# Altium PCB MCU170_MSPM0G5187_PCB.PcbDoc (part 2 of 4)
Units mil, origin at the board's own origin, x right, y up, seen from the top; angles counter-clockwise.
Board outline 2300 x 4450 mil, 4 copper layers (Top Layer, VCC Layer, GND Layer, Bottom Layer), stack 62.4 mil thick; 276 components, 190 nets, 913 pads, 323 vias.
Unrouted connection lines stored in the file: 4.
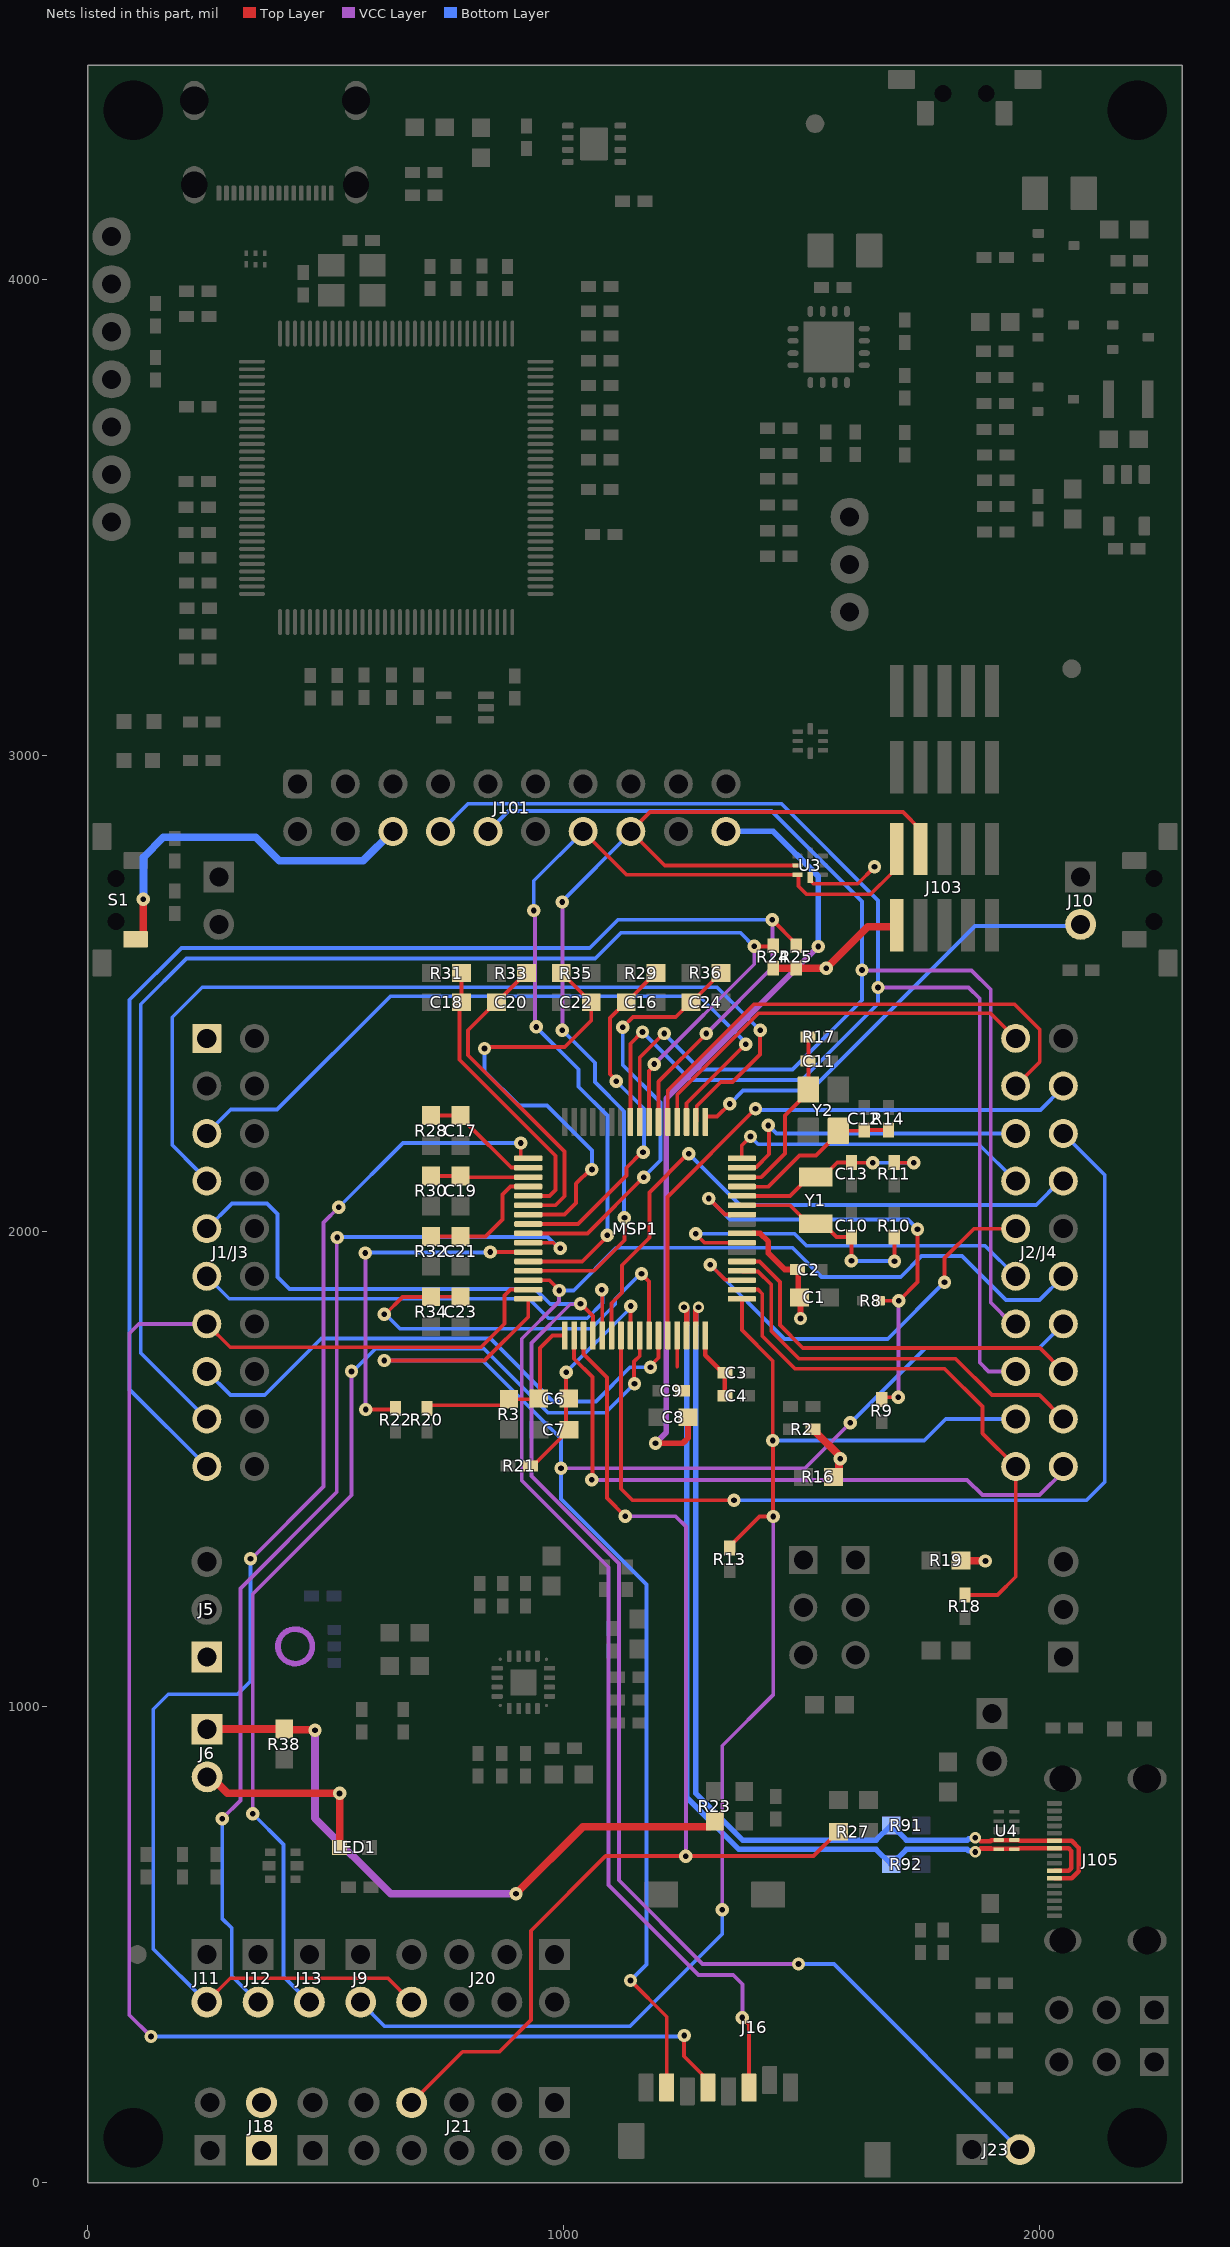
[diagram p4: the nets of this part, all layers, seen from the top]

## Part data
C1 C35 C69: library part CMP-0007304-1, "CAP, CERM, 10 uF, 6.3 V, +/- 20%, X5R, 0603", Cap_Case=0603, Manufacturer=MuRata, Supplier Part Number 1=490-7316-1-ND, TempCo=X5R, Tolerance_%=20%, Value1=Unknown, Value2=6.3V, ValueDisplayed=10uF
C2 C9 C31 C72 C73 C74 C75: library part CMP-0006614-2, "CAP, CERM, 0.1 uF, 50 V, +/- 20%, X5R, 0402", Cap_Case=0402, Manufacturer=MuRata, Supplier Part Number 1=GRM155R61H104ME14D-ND, TempCo=X5R, Tolerance_%=20%, Value1=Unknown, Value2=50V, ValueDisplayed=0.1uF
C3: library part CMP-0006551-2, "CAP, CERM, 0.47 uF, 6.3 V, +/- 10%, X5R, 0402", Cap_Case=0402, Manufacturer=MuRata, Supplier Part Number 1=490-3266-1-ND, TempCo=X5R, Tolerance_%=10%, Value1=Unknown, Value2=6.3V, ValueDisplayed=0.47uF
C4: library part CMP-0006614-2, "CAP, CERM, 0.1 uF, 50 V, +/- 20%, X5R, 0402", Cap_Case=0402, Manufacturer=MuRata, Supplier Part Number 1=GRM155R61H104ME14D-ND, TempCo=X5R, Tolerance_%=20%, Value1=Unknown, Value2=50V, ValueDisplayed=DNC
C5: library part CMP-0006590-2, "CAP, CERM, 0.01 uF, 16 V, +/- 10%, X5R, 0402", Cap_Case=0402, Manufacturer=MuRata, Supplier Part Number 1=GRM155R61C103KA01D-ND, TempCo=X5R, Tolerance_%=10%, Value1=Unknown, Value2=16V, ValueDisplayed=0.01uF
C6 C7 C8: library part CMP-0007006-5, "CAP, CERM, 1 uF, 25 V, +/- 10%, X5R, 0603", Cap_Case=0603, Manufacturer=TDK, Supplier Part Number 1=445-5146-1-ND, TempCo=X5R, Tolerance_%=10%, Value1=Unknown, Value2=25V, ValueDisplayed=DNC
C10 C11 C12 C13: library part CMP-0006420-2, "CAP, CERM, 15 pF, 50 V, +/- 5%, C0G/NP0, 0402", Cap_Case=0402, Manufacturer=MuRata, Supplier Part Number 1=81-GRM1555C1H150JA1D, TempCo=C0G/NP0, Tolerance_%=5%, Value1=Unknown, Value2=50V, ValueDisplayed=15pF
C14: library part CMP-0078241-1, "CAP, CERM, 0.1 µF, 10 V,+/- 10%, X7R, 0402", Cap_Case=0402, Manufacturer=Kemet, Supplier Part Number 1=399-3520-1-ND, TempCo=X7R, Tolerance_%=10%, Value2=10V, ValueDisplayed=0.1µF
C15 C36: library part CMP-0007122-5, "CAP, CERM, 10 uF, 16 V, +/- 20%, X5R, 0603", Cap_Case=0603, Manufacturer="Taiyo Yuden", Supplier Part Number 1=587-3238-1-ND, TempCo=X5R, Tolerance_%=20%, Value1=Unknown, Value2=16V, ValueDisplayed=10uF
C16 C17 C18 C19 C20 C21 C22 C23 C24: library part CMP-0007135-4, "CAP, CERM, 0.1 uF, 16 V, +/- 10%, X7R, AEC-Q200 Grade 1, 0603", Cap_Case=0603, Manufacturer=MuRata, Supplier Part Number 1=490-8015-1-ND, TempCo=X7R, Tolerance_%=10%, Value1=Unknown, Value2=16V, ValueDisplayed=0.1uF
C25 C26 C33 C34: library part CMP-0006563-2, "CAP, CERM, 1 uF, 10 V, +/- 10%, X5R, 0402", Cap_Case=0402, Manufacturer=MuRata, Supplier Part Number 1=490-3890-1-ND, TempCo=X5R, Tolerance_%=10%, Value1=Unknown, Value2=10V, ValueDisplayed=1uF
C27 C28 C29: library part CMP-0007023-4, "CAP, CERM, 10 uF, 10 V, +/- 10%, X6S, 0603", Cap_Case=0603, Manufacturer=TDK, Supplier Part Number 1=445-9019-1-ND, TempCo=X6S, Tolerance_%=10%, Value1="0.004639 ohm", Value2=10V, ValueDisplayed=10uF
C30 C32: library part CMP-0007037-4, "CAP, CERM, 1 uF, 16 V, +/- 10%, X7R, 0603", Cap_Case=0603, Manufacturer=TDK, Supplier Part Number 1=445-1604-1-ND, TempCo=X7R, Tolerance_%=10%, Value1="0.0057 ohm", Value2=16V, ValueDisplayed=1uF
C37 C41 C42 C44 C48 C51 C52 C57 C62 C63 C68: library part CMP-0006623-2, "CAP, CERM, 0.1 uF, 6.3 V, +/- 10%, X7R, 0402", Cap_Case=0402, Manufacturer=MuRata, Supplier Part Number 1=GRM155R70J104KA01D-ND, TempCo=X7R, Tolerance_%=10%, Value1=Unknown, Value2=6.3V, ValueDisplayed=0.1uF
C38 C39 C40 C46 C50: library part CMP-0006658-2, "CAP, CERM, 0.01 uF, 25 V, +/- 10%, X7R, 0402", Cap_Case=0402, Manufacturer=MuRata, Supplier Part Number 1=490-1312-1-ND, TempCo=X7R, Tolerance_%=10%, Value1=Unknown, Value2=25V, ValueDisplayed=0.01uF
C43 C45 C49 C70: library part CMP-0006276-2, "CAP, CERM, 1 uF, 25 V, +/- 10%, X5R, 0402", Cap_Case=0402, Manufacturer=TDK, Supplier Part Number 1=445-9066-1-ND, TempCo=X5R, Tolerance_%=10%, Value1=Unknown, Value2=25V, ValueDisplayed=1uF
C47 C71: library part CMP-0006543-2, "CAP, CERM, 2.2 uF, 6.3 V, +/- 10%, X5R, 0402", Cap_Case=0402, Manufacturer=MuRata, Supplier Part Number 1=81-GRM155R60J225KE5D, TempCo=X5R, Tolerance_%=10%, Value1=Unknown, Value2=6.3V, ValueDisplayed=2.2uF
C53 C54: library part CMP-0006415-2, "CAP, CERM, 12 pF, 50 V, +/- 5%, C0G/NP0, 0402", Cap_Case=0402, Manufacturer=MuRata, Supplier Part Number 1=14T3292, TempCo=C0G/NP0, Tolerance_%=5%, Value1=Unknown, Value2=50V, ValueDisplayed=12pF
C55 C58: library part CMP-0006454-1, "CAP, CERM, 33 pF, 50 V, +/- 5%, C0G/NP0, 0402", Cap_Case=0402, Manufacturer=MuRata, Supplier Part Number 1=81-GRM1555C1H330JA1D, TempCo=C0G/NP0, Tolerance_%=5%, Value1=Unknown, Value2=50V, ValueDisplayed=33pF
C56 C60: library part CMP-0011480-1, "CAP, TA, 4.7 uF, 16 V, +/- 10%, 4 ohm, SMD", Cap_Case=3216-18, Manufacturer=AVX, Supplier Part Number 1=478-3868-1-ND, Tolerance_%=10%, Value1="4 ohm", Value2=16V, ValueDisplayed=4.7uF
C59: library part CMP-0006354-2, "CAP, CERM, 1000 pF, 50 V, +/- 10%, X7R, AEC-Q200 Grade 1, 0402", Cap_Case=0402, Manufacturer=MuRata, Supplier Part Number 1=490-4761-1-ND, TempCo=X7R, Tolerance_%=10%, Value1=Unknown, Value2=50V, ValueDisplayed=1000pF
C61 C67: library part CMP-0007341-4, "CAP, CERM, 4.7 uF, 16 V, +/- 10%, X5R, 0603", Cap_Case=0603, Manufacturer=MuRata, Supplier Part Number 1=490-10481-1-ND, TempCo=X5R, Tolerance_%=10%, Value1=Unknown, Value2=16V, ValueDisplayed=4.7uF
C64: library part CMP-0007313-1, "CAP, CERM, 47 uF, 6.3 V, +/- 20%, X5R, 0603", Cap_Case=0603, Manufacturer=MuRata, TempCo=X5R, Tolerance_%=20%, Value1=Unknown, Value2=6.3V, ValueDisplayed=47uF
C65 C66: library part CMP-0006648-1, "CAP, CERM, 0.22 uF, 16 V, +/- 10%, X7R, 0402", Cap_Case=0402, Manufacturer=MuRata, Supplier Part Number 1=490-5418-1-ND, TempCo=X7R, Tolerance_%=10%, Value1=Unknown, Value2=16V, ValueDisplayed=0.22uF
C76 C77: library part CMP-0081457-1, "CAP, CERM, 1 µF, 10 V,+/- 20%, X5R, 0402", Cap_Case=0402, Manufacturer="Yageo America", TempCo=X5R, Tolerance_%=20%, Value2=10V, ValueDisplayed=1µF
D1 D2: library part CMP-0028883-1, "Diode, Schottky, 40 V, 0.12 A, AEC-Q101, SOT-323", Manufacturer=Nexperia, Supplier Part Number 1=568-7982-1-ND, Value1=0.12A, Value2=1V
FID1 FID2 FID3: library part CMP-0077181-1, "Fiducial mark.  There is nothing to buy or mount.", Manufacturer=N/A
H1 H2: library part CMP-0077978-1, "Spacer Support, Nylon 66", Manufacturer="Kang Yang"
IC2: library part CMP-0032790-2, "Precision Micropower Shunt Voltage Reference, 0.5% accuracy, 2.5 V, 15 ppm / degC, 15 mA, -40 to 85 degC, 5-pin SC70 (DCK), Green (RoHS & no Sb/Br)", Manufacturer="Texas Instruments", Rating=Catalog, Temp Coeff(Max)(ppm/ degree C)=100, Temp Coeff(Typ)(ppm/ degree C)=15
IC3: library part CMP-0074212-1, "2.7-4V Dual In/Single Out MOSFET, 0.5A Main/0.1A Aux Input, Act-Low Enable, Comm. Temp., DBV0005A (SOT-23-5)", Alternate Manufacturer="Texas Instruments", Alternate PartNumber=TPS2102DBVT
IC4 U3: library part CMP-0043125-2, "Low-Capacitance + / - 15 kV ESD Protection Array for High-Speed Data Interfaces, 6 Channels, -40 to +85 degC, 8-pin UQFN (RSE), Green (RoHS & no Sb/Br)", Breakdown Voltage(Min)(V)=6, IO Capacitance(Typ)(pF)=1.6, IO Leakage Current(nA)=1, Manufacturer="Texas Instruments"
IC5: library part CMP-0043115-1, "ESD-Protection Array for High-Speed Data Interfaces, 4 Channels, -40 to +85 degC, 6-pin SON (DRY), Green (RoHS & no Sb/Br)", Breakdown Voltage(Min)(V)=6, IO Capacitance(Typ)(pF)=1.6, IO Leakage Current(nA)=1, Manufacturer="Texas Instruments"
IC6: library part CMP-0036329-3, "500mA, Adjustable, Low Quiescent Current, Low-Noise, High-PSRR, Single-Output LDO Regulator, DRB0008A (VSON-8)", Manufacturer="Texas Instruments", Operating Temperature Range="-40 to 125 C", Rating=Catalog
J1/J3: library part CMP-0003837-4, "Receptacle, 2.54mm, 10x2, Tin, TH", Alternate Manufacturer="Major League Electronics", Alternate PartNumber=CRD-081413-A-G, Manufacturer=Samtec, Supplier Part Number 1=SAM1204-10-ND
J2/J4: library part CMP-0078266-4, "Receptacle, 2.54mm, 10x2, Tin, TH", Alternate Manufacturer="Major League Electronics", Alternate PartNumber=CRD-081413-A-G, Manufacturer=Samtec, Supplier Part Number 1=SAM1204-10-ND
J5 J7 J14 J15 J24 J25: library part CMP-0002338-1, "Header, 100mil, 3x1, Tin, TH", Color=Black, Current_A=3A, Manufacturer="Sullins Connector Solutions", Supplier Part Number 1=S1012E-03-ND, Voltage_V=1.8kV
J6 J8 J9 J10 J11 J12 J13 J17 J18 J19 J22 J23: library part CMP-0055312-1, "Header, 100mil, 2x1, Tin, TH", Manufacturer=Molex, Supplier Part Number 1=WM8072-ND
J16: library part CMP-0089421-1, "9 (8 + 1) Position Card Connector Secure Digital - microSD™ Surface Mount, Right Angle Gold", Current_A=500mA, Digikey Part Number=732-3819-1-ND, Manufacturer="Wurth Electronics", Mouser Part Number=710-693071010811, Operating Temperature Range="-25°C to +85°C", Voltage_V=100V
J20: library part CMP-0054542-2, "Header, 100mil, 4x2, Tin, TH", Color=Black, Current_A=3A, Manufacturer="Sullins Connector Solutions", Supplier Part Number 1=S2012E-04-ND, Voltage_V=1.8kV
J21: library part CMP-0054550-2, "Header, 100mil, 5x2, Tin, TH", Color=Black, Current_A=3A, Manufacturer="Sullins Connector Solutions", Supplier Part Number 1=S2012E-05-ND, Voltage_V=1.8kV
J101: library part CMP-0054623-2, "Header, 2.54mm, 10x2, Tin, TH", Color=Black, Current_A=3A, Manufacturer="Sullins Connector Solutions", Supplier Part Number 1=S2012E-10-ND
J102 J103: library part CMP-0075634-1, "Header(Shrouded), 1.27mm, 5x2, Gold, SMT", Color=Black, Current_A=3.3A, Manufacturer=Samtec, Supplier Part Number 1=SAM8799-ND
J104 J105: library part CMP-0092121-1, "16PIN USB C connectors in chargers TOP mount type CH 1.63 & L=6.9 USB Type C connectors", Current_A=5A, Manufacturer=MUP, Operating Temperature Range=to
L1: library part CMP-0059590-1, "Inductor, Wirewound, Ceramic, 2.2 uH, 0.89 A, 0.13 ohm, SMD", Manufacturer="Taiyo Yuden", Supplier Part Number 1=587-1618-1-ND, Value1="0.13 ohm", Value2=0.89A, ValueDisplayed=2.2uH
LED1 LED3 LED101: library part CMP-0002972-3, "LED, Red, SMD", Color=Red, Manufacturer="Stanley Electric Co., LTD", Power_TotalModule=57.5mW, Value1=0.0575W, Value2=1.7V
LED2: library part CMP-0074720-1, "LED, RGB, SMD", Color=RGB, Manufacturer=Everlight, Supplier Part Number 1=19-337/R6GHBHC-A01/2T-ND, Value1=W, Value2=3.8V
LED102: library part CMP-0002827-3, "LED, Green, SMD", Color=green, Manufacturer=Lite-On, Power_TotalModule=100mW, Value1=0.1W, Value2=2.1V
LOGO1: library part CMP-0074844-1
Logo2 Logo3: library part CMP-0074838-1, "Texas Instrument Corporate Signature"
Logo4: library part CMP-0074840-1, "ESD Susceptible Symbol"
Logo5: library part CMP-0074847-1, "FCC_disclaimer"
Logo6: library part CMP-0074769-1
MH1 MH2 MH3 MH4: library part CMP-0078424-2, "PCB Mounting Hole, No Pad", Manufacturer=Any, PartNumber=N/A
MSP1: library part CMP-0125668-4, "Mixed-Signal Microcontrollers With USB 2.0-FS Interface and NPU", Frequency_Fixed=80MHz, Manufacturer="Texas Instruments", Max Supply Voltage=3.6V, Min Supply Voltage=1.62V, Operating Temperature Range="-40°C to +125°C"
R1 R2 R40 R42 R43 R44: library part CMP-0026935-1, "RES, 47 k, 5%, 0.063 W, 0402", Manufacturer=Vishay-Dale, Power_W=63mW, Supplier Part Number 1=541-47KJCT-ND, TempCo="200 ppm/C", Tolerance_%=5%, Value2=0.063W, Value_Code=47k0, ValueDisplayed=47k
R3 R23 R38: library part CMP-0025885-5, "RES, 0, 5%, 0.1 W, 0603", Manufacturer=Yageo, Power_W=100mW, Supplier Part Number 1=311-0.0GRCT-ND, TempCo="200 ppm/C", Tolerance_%=5%, Value2=0.1W, Value_Code=0000, ValueDisplayed=DNC
R4 R57 R58: library part CMP-0026934-2, "RES, 470, 5%, 0.063 W, 0402", Manufacturer=Vishay-Dale, Power_W=63mW, Supplier Part Number 1=541-470JCT-ND, TempCo="200 ppm/C", Tolerance_%=5%, Value2=0.063W, Value_Code=470R, ValueDisplayed=470
R5: library part CMP-0026878-1, "RES, 220, 5%, 0.063 W, 0402", Manufacturer=Vishay-Dale, Power_W=63mW, Supplier Part Number 1=541-220JCT-ND, TempCo="200 ppm/C", Tolerance_%=5%, Value2=0.063W, Value_Code=220R, ValueDisplayed=220
R6 R7: library part CMP-0026906-1, "RES, 330, 5%, 0.063 W, 0402", Manufacturer=Vishay-Dale, Power_W=63mW, Supplier Part Number 1=541-330JCT-ND, TempCo="200 ppm/C", Tolerance_%=5%, Value2=0.063W, Value_Code=330R, ValueDisplayed=330
R8: library part CMP-0088648-1, "Res Thin Film 0402 100K Ohm 0.1% 1/16W ±25ppm/°C Molded SMD SMD Punched Carrier T/R", Digikey Part Number=P100KDCCT-ND, Manufacturer=Panasonic, Mouser Part Number=667-ERA-2AEB104X, Octopart Part Number=aea26725a1f47165, Operating Temperature Range="-55°C to +155°C", Power_W=63mW, TempCo=25ppm/°C, Tolerance_%=0.1%, Voltage=25V
R9 R10 R11 R14 R17 R20 R21: library part CMP-0027004-2, "RES, 0, 5%, 0.063 W, 0402", Manufacturer="Yageo America", Power_W=63mW, Supplier Part Number 1=311-0.0JRCT-ND, TempCo="200 ppm/C", Tolerance_%=5%, Value2=0.063W, Value_Code=0000, ValueDisplayed=DNC
R12 R15 R27: library part CMP-0025927-5, "RES, 4.7 k, 5%, 0.1 W, 0603", Manufacturer=Yageo, Power_W=100mW, Supplier Part Number 1=311-4.7KGRCT-ND, TempCo="100 ppm/C", Tolerance_%=5%, Value2=0.1W, Value_Code=4k70, ValueDisplayed=4.7k
R13 R18: library part CMP-0026886-1, "RES, 270, 5%, 0.063 W, 0402", Manufacturer=Vishay-Dale, Power_W=63mW, Supplier Part Number 1=541-270JCT-ND, TempCo="200 ppm/C", Tolerance_%=5%, Value2=0.063W, Value_Code=270R, ValueDisplayed=270
R16 R19: library part CMP-0025906-5, "RES, 2.2 k, 5%, 0.1 W, 0603", Manufacturer=Yageo, PartNumber=RC0603JR-072K2L, Power_W=100mW, Supplier Part Number 1=311-2.2KGRCT-ND, TempCo="100 ppm/C", Tolerance_%=5%, Value2=0.1W, Value_Code=2k20, ValueDisplayed=2.2k
R22: library part CMP-0027004-2, "RES, 0, 5%, 0.063 W, 0402", Manufacturer="Yageo America", Power_W=63mW, Supplier Part Number 1=311-0.0JRCT-ND, TempCo="200 ppm/C", Tolerance_%=5%, Value2=0.063W, Value_Code=0000
R24 R25: library part CMP-0026938-5, "RES, 4.7 k, 5%, 0.063 W, AEC-Q200 Grade 0, 0402", Manufacturer=Vishay-Dale, Power_W=63mW, Supplier Part Number 1=541-4.7KJCT-ND, TempCo="200 ppm/C", Tolerance_%=5%, Value2=0.063W, Value_Code=4k70, ValueDisplayed=DNC
R26: library part CMP-0025925-5, "RES, 47 k, 5%, 0.1 W, 0603", Manufacturer=Yageo, Power_W=100mW, Supplier Part Number 1=311-47KGRCT-ND, TempCo="100 ppm/C", Tolerance_%=5%, Value2=0.1W, Value_Code=47k0, ValueDisplayed=47k
R28 R30 R32 R34: library part CMP-0022928-4, "RES, 22.0, 1%, 0.1 W, 0603", Manufacturer=Yageo, Power_W=100mW, Supplier Part Number 1=311-22.0HRCT-ND, TempCo="100 ppm/C", Tolerance_%=1%, Value2=0.1W, Value_Code=22R0, ValueDisplayed=22.0
R29 R31 R33 R35 R36 R80 R84 R91 R92: library part CMP-0025885-5, "RES, 0, 5%, 0.1 W, 0603", Manufacturer=Yageo, Power_W=100mW, Supplier Part Number 1=311-0.0GRCT-ND, TempCo="200 ppm/C", Tolerance_%=5%, Value2=0.1W, Value_Code=0000, ValueDisplayed=0
R37 R39 R41: library part CMP-0027004-2, "RES, 0, 5%, 0.063 W, 0402", Manufacturer="Yageo America", Power_W=63mW, Supplier Part Number 1=311-0.0JRCT-ND, TempCo="200 ppm/C", Tolerance_%=5%, Value2=0.063W, Value_Code=0000, ValueDisplayed=0
R45 R85: library part CMP-0026731-1, "RES, 330 k, 1%, 0.0625 W, 0402", Manufacturer="Yageo America", Power_W=62.5mW, Supplier Part Number 1=311-330KLRCT-ND, TempCo="100 ppm/C", Tolerance_%=1%, Value2=0.0625W, Value_Code=330k
R46 R64 R65 R71 R72 R79 R82 R87: library part CMP-0026728-1, "RES, 220 k, 1%, 0.0625 W, 0402", Manufacturer="Yageo America", Power_W=62.5mW, Supplier Part Number 1=311-220KLRCT-ND, TempCo="100 ppm/C", Tolerance_%=1%, Value2=0.0625W, Value_Code=220k
R47 R48: library part CMP-0026752-1, "RES, 56.0 k, 1%, 0.063 W, AEC-Q200 Grade 0, 0402", Manufacturer="KOA Speer", Power_W=63mW, Supplier Part Number 1=660-RK73H1ETTP5602F, TempCo="100 ppm/C", Tolerance_%=1%, Value2=0.063W, Value_Code=56k0, ValueDisplayed=56.0k
R49 R50 R86 R88: library part CMP-0026463-2, "RES, 5.11 k, 1%, 0.063 W, AEC-Q200 Grade 0, 0402", Manufacturer=Vishay-Dale, Power_W=63mW, Supplier Part Number 1=541-5.11KLCT-ND, TempCo="100 ppm/C", Tolerance_%=1%, Value2=0.063W, Value_Code=5k11, ValueDisplayed=5.11k
R51: library part CMP-0078193-1, "RES, 1.0 k, 5%, 0.1 W, AEC-Q200 Grade 0, 0402", Manufacturer=Panasonic, Power_W=100mW, Supplier Part Number 1=P1.0KJCT-ND, TempCo="200 ppm/C", Tolerance_%=5%, Value2=0.1W, Value_Code=1k00, ValueDisplayed=1.0k
R52 R53 R54 R62: library part CMP-0026852-1, "RES, 1.0 k, 5%, 0.063 W, 0402", Manufacturer=Vishay-Dale, Power_W=63mW, Supplier Part Number 1=541-1.0KJCT-ND, TempCo="200 ppm/C", Tolerance_%=5%, Value2=0.063W, Value_Code=1k00, ValueDisplayed=1.0k
R55: library part CMP-0026852-1, "RES, 1.0 k, 5%, 0.063 W, 0402", Manufacturer=Vishay-Dale, Power_W=63mW, Supplier Part Number 1=541-1.0KJCT-ND, TempCo="200 ppm/C", Tolerance_%=5%, Value2=0.063W, Value_Code=1k00, ValueDisplayed=DNC
R56: library part CMP-0026824-3, "RES, 100, 5%, 0.063 W, AEC-Q200 Grade 0, 0402", Manufacturer=Vishay-Dale, Power_W=63mW, Supplier Part Number 1=541-100JCT-ND, TempCo="200 ppm/C", Tolerance_%=5%, Value2=0.063W, Value_Code=100R, ValueDisplayed=100
R59 R89 R90: library part CMP-0026825-4, "RES, 10 k, 5%, 0.063 W, 0402", Manufacturer=Vishay-Dale, Power_W=63mW, Supplier Part Number 1=541-10KJCT-ND, TempCo="200 ppm/C", Tolerance_%=5%, Value2=0.063W, Value_Code=10k0, ValueDisplayed=10k
R60: library part CMP-0026413-2, "RES, 4.87 k, 1%, 0.063 W, AEC-Q200 Grade 0, 0402", Manufacturer=Vishay-Dale, Power_W=63mW, Supplier Part Number 1=541-4.87KLCT-ND, TempCo="100 ppm/C", Tolerance_%=1%, Value2=0.063W, Value_Code=4k87, ValueDisplayed=4.87k
R61: library part CMP-0026824-1, "RES, 100, 5%, 0.063 W, 0402", Manufacturer=Vishay-Dale, Power_W=63mW, Supplier Part Number 1=541-100JCT-ND, TempCo="200 ppm/C", Tolerance_%=5%, Value2=0.063W, Value_Code=100R, ValueDisplayed=100
R63: library part CMP-0026946-3, "RES, 51, 5%, 0.063 W, AEC-Q200 Grade 0, 0402", Manufacturer=Vishay-Dale, Power_W=63mW, Supplier Part Number 1=541-51JCT-ND, TempCo="200 ppm/C", Tolerance_%=5%, Value2=0.063W, Value_Code=51R0, ValueDisplayed=51
R66 R83: library part CMP-0026695-1, "RES, 3.30 k, 1%, 0.1 W, AEC-Q200 Grade 0, 0402", Manufacturer=Panasonic, Power_W=100mW, Supplier Part Number 1=P3.30KLCT-ND, TempCo="100 ppm/C", Tolerance_%=1%, Value2=0.1W, Value_Code=3k30, ValueDisplayed=3.30k
R67: library part CMP-0026231-1, "RES, 2.20 k, 1%, 0.063 W, 0402", Manufacturer=Vishay-Dale, Power_W=63mW, Supplier Part Number 1=541-2.20KLCT-ND, TempCo="100 ppm/C", Tolerance_%=1%, Value2=0.063W, Value_Code=2k20, ValueDisplayed=2.20k
R68: library part CMP-0026517-1, "RES, 6.81 k, 1%, 0.063 W, 0402", Manufacturer=Vishay-Dale, Power_W=63mW, Supplier Part Number 1=541-6.81KLCT-ND, TempCo="100 ppm/C", Tolerance_%=1%, Value2=0.063W, Value_Code=6k81, ValueDisplayed=6.81k
R69 R70: library part CMP-0026938-1, "RES, 4.7 k, 5%, 0.063 W, 0402", Manufacturer=Vishay-Dale, Power_W=63mW, Supplier Part Number 1=541-4.7KJCT-ND, TempCo="200 ppm/C", Tolerance_%=5%, Value2=0.063W, Value_Code=4k70, ValueDisplayed=4.7k
R73 R74 R77: library part CMP-0026737-1, "RES, 47.0 k, 1%, 0.0625 W, 0402", Manufacturer="Yageo America", Power_W=62.5mW, Supplier Part Number 1=311-47.0KLRCT-ND, TempCo="100 ppm/C", Tolerance_%=1%, Value2=0.0625W, Value_Code=47k0, ValueDisplayed=47.0k
R75: library part CMP-0026743-1, "RES, 820, 1%, 0.063 W, 0402", Manufacturer="Yageo America", Power_W=63mW, Supplier Part Number 1=311-820LRCT-ND, TempCo="100 ppm/C", Tolerance_%=1%, Value2=0.063W, Value_Code=820R, ValueDisplayed=820
R76: library part CMP-0026934-1, "RES, 470, 5%, 0.063 W, 0402", Manufacturer=Vishay-Dale, Power_W=63mW, Supplier Part Number 1=541-470JCT-ND, TempCo="200 ppm/C", Tolerance_%=5%, Value2=0.063W, Value_Code=470R, ValueDisplayed=470
R78 R81: library part CMP-0026728-1, "RES, 220 k, 1%, 0.0625 W, 0402", Manufacturer="Yageo America", Power_W=62.5mW, Supplier Part Number 1=311-220KLRCT-ND, TempCo="100 ppm/C", Tolerance_%=1%, Value2=0.0625W, Value_Code=220k, ValueDisplayed=DNC
S1 S2 S3: library part CMP-0002328-1, "Switch, SPST, 0.05 A, 12 VDC, SMD", CurrentRating_mA=50A, Manufacturer=Diptronics
SH-J1 SH-J2 SH-J3 SH-J4 SH-J5 SH-J6 SH-J7 SH-J8 SH-J9 SH-J10 SH-J11 SH-J12 SH-J13 SH-J14 SH-J15 SH-J16 SH-J17 SH-J18 SH-J19 SH-J20 SH-J21 SH-J22 SH-J23: library part CMP-0003623-3, "Shunt, 100mil, Gold plated, Black", Alternate Manufacturer=3M, Alternate PartNumber=969102-0000-DA, Manufacturer=Samtec, Supplier Part Number 1=SAM8858-ND
T1: library part CMP-0000035-1, "MOSFET, P-CH, -20 V, -0.82 A, SOT-323", Alternate Manufacturer=None, Manufacturer="Diodes Inc.", Supplier Part Number 1=DMG1013UW-7DICT-ND, Value1=0.7, Value2="0.622 nC"
T2: library part CMP-0000466-1, "Transistor, NPN, 45 V, 0.1 A, SOT-323", Manufacturer="NXP Semiconductor", Supplier Part Number 1=568-6076-1-ND, Value1="0.1 A", Value2=800
TP1 TP2 TP3 TP4 TP5 TP6 TP7 TP8 TP9 TP10: library part CMP-0055138-1, "Test Point, Miniature, Black, TH", Color=Black, Manufacturer=Keystone, Supplier Part Number 1=36-5001-ND
U1: library part CMP-0121894-1, "Stereo Channel, 32-Bit, 192-kHz, Burr-Brown Audio ADC", Manufacturer="Texas Instruments", Max Supply Voltage=3.6V, Min Supply Voltage=1.65V, Operating Temperature Range="-40°C to +125°C"
U2: library part CMP-0078776-1, "Ultra-Low Noise Microphone with Differential Output, LGA-4", Manufacturer=InvenSense, Supplier Part Number 1=1428-1120-1-ND
U4: library part CMP-0073613-3, "4-Channel Ultra-Low-Capacitance IEC ESD Protection Diode, DQA0010A (USON-10)", Alternate Manufacturer="Texas Instruments"
XDS1: library part CMP-0077954-1, "MSP432E401YTPDT, PDT0128A (TQFP-128)", Alternate Manufacturer="Texas Instruments", Alternate PartNumber=MSP432E401YTPDT
XDS2: library part CMP-0039611-2, "MSP430G2x52, MSP430G2x12 Mixed Signal Microcontroller, RSA0016B (VQFN-16)", Alternate PartNumber=MSP430G2452IRSA16T, Frequency(MHz)=16, Manufacturer="Texas Instruments", Operating Temperature Range="-40 to 85 C", Rating=Catalog, Temp Sensor=Yes
Y1: library part CMP-0004693-2, "Crystal, 32.768 KHz, 12.5 pF, SMD", Frequency_Fixed=32.768kHz, Manufacturer=Epson
Y2: library part CMP-0098168-2, "Crystal 40MHz ±10ppm (Tol) ±20ppm (Stability) 12pF FUND 40Ohm 4-Pin Mini-CSMD T/R", Frequency Stability=20ppm, Frequency Tolerance=10ppm, Frequency_Fixed=40MHz, Load Capacitance=12pF, Manufacturer="Seiko Epson", Operating Temperature Range="-40°C to +105°C"
Y3: library part CMP-0004635-1, "Crystal, 16 MHz, 8pF, SMD", Frequency_Fixed=16MHz, Frequency Stability=+/-30ppm, Manufacturer=NDK, Supplier Part Number 1=644-1157-1-ND
ZZ2 ZZ3 ZZ4: library part AssemblyNote, Alternate Manufacturer=-

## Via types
v1: diameter 28, hole 12, Top Layer to Bottom Layer, 291 vias
v2: diameter 19.68, hole 7.87, Top Layer to Bottom Layer, 9 vias
v3: diameter 36, hole 20, Top Layer to Bottom Layer, 8 vias
v4: diameter 24, hole 12, Top Layer to Bottom Layer, 4 vias
v5: diameter 24, hole 12, Top Layer to Bottom Layer, tented both sides, 4 vias
v6: diameter 19.68, hole 7.87, Top Layer to Bottom Layer, tented both sides, 4 vias
v7: diameter 28, hole 12, Top Layer to Bottom Layer, tented both sides, 2 vias
v8: diameter 39.37, hole 39.37, Top Layer to Bottom Layer, 1 vias

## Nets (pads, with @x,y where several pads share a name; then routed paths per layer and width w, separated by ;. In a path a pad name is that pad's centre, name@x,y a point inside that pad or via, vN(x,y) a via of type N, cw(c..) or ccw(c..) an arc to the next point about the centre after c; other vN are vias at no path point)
1_PB13_RGBLED: J11.2 J20.8 MSP1.1 | length 2922.8
  Top Layer w8: J11.2@249.17,379.62 299.17,429.62 630.54,429.62 J20.8@680.54,379.62 ; v1(909.95,2185.03) 909.95,2154.54 911.85,2152.64 MSP1.1@925.59,2152.64
  VCC Layer w8: v1(341.9,1311.5) 343.8,1311.5 495.24,1462.94 495.24,2017.86 v1(527.43,2050.05)
  Bottom Layer w8: J11.2@249.17,379.62 137.48,491.31 137.48,995.09 169.03,1026.64 314.68,1026.64 341.9,1053.86 v1(341.9,1311.5) ; v1(527.43,2050.05) 662.42,2185.03 v1(909.95,2185.03)
2_PB14_A0_21: C17.2 MSP1.2 R28.2 | length 251.6
  Top Layer w8: R28.2@721.22,2242.74 C17.2@783.43,2242.74 798.13,2228.04 798.13,2225.01 889.83,2133.3 925.24,2133.3 MSP1.2@925.59,2132.95
3.3VM: J6.1 R23.1 R38.2 | length 1381.8
  Top Layer w16: J6.1@250.54,953.54 412.77,953.54 414.12,952.2 476.2,952.2 v1(477.35,951.06) ; v1(899.68,607.36) 1040.63,748.31 1306.88,748.31 1317.59,759.01 R23.1@1317.59,759.41
  VCC Layer w16: v1(477.35,951.06) 477.35,766.4 636.38,607.36 v1(899.68,607.36)
3_PB15_A0_20: C19.2 MSP1.3 R30.2 | length 205.4
  Top Layer w8: R30.2@721.22,2115.77 C19.2@783.43,2115.77 785.93,2113.27 MSP1.3@925.59,2113.27
3V3: C1.1 C2.1 J1/J3.1 J5.1 J6.2 J18.1 J18.2 J101.6 J103.1 LED1.1 MSP1.40 R2.2 R16.2 R19.2 R24.1 R25.1 S1.4 U3.8 | length 2272.3
  Top Layer w8: U3.8@1517.93,2742.9 1517.93,2736.99 1524.98,2729.94 1617.93,2729.94 v1(1653.36,2765.37)
  Top Layer w12: MSP1.40@1397.94,1995.12 1412.88,1995.12 1430.25,1977.75 1430.25,1953.22 1464.46,1919.01 C2.1@1491.9,1919.01 ; C2.1@1492.73,1918.17 1492.73,1863.38 C1.1@1495.5,1860.62 ; v1(1497.71,1816.15) C1.1@1497.71,1860.62
  Top Layer w16: S1.4@116.49,2616.36 v1(116.49,2697.29) ; J6.2@250.8,853 258.69,853 293.52,818.18 v1(529.13,818.18) 529.07,818.12 LED1.1@529.07,704.89 ; R24.1@1440.68,2552.35 1440.76,2552.44 R25.1@1488.69,2552.35 1488.8,2552.33 v1@1551.74,2552.33 ; R2.2@1523.91,1583.28 1527.84,1583.28 1531.65,1579.47 1531.65,1575.53 1578.89,1528.29 1578.89,1524.04 v1(1581.19,1521.74) 1581.19,1518.49 1578.68,1515.98 1578.68,1493.98 1567.97,1483.28 R16.2@1566.99,1483.28 ; v1(1551.77,2552.3) 1639.02,2639.55 1693.43,2639.55 1696.76,2642.88 J103.1@1700,2642.88 ; R19.2@1835.2,1307.91 1835.81,1307.31 1885.73,1307.31 v1(1886.34,1306.71)
  VCC Layer w11.81: 471.98,1127.17 ccw(c435.76,1127.17) 471.98,1127.17
  Bottom Layer w16: v1@117.05,2697.84 117.05,2785.6 158.87,2827.42 352.82,2827.42 402.37,2777.87 578.27,2777.87 J101.6@640.4,2840
4_PB16_A0_19: C21.2 MSP1.4 R32.2 | length 278.4
  Top Layer w8: R32.2@721.22,1988.79 C21.2@783.43,1988.79 835.68,1988.79 871.25,2024.36 871.25,2076.73 888.11,2093.58 MSP1.4@925.59,2093.58
5_PA12_I2S_BCLK_A0_18: C18.2 MSP1.5 R31.2 | length 603.7
  Top Layer w8: R31.2@785.38,2542.28 C18.2@785.38,2480.87 780.97,2476.46 780.97,2359.97 982.83,2158.11 982.83,2086.52 970.2,2073.9 MSP1.5@925.59,2073.9
6_PA13_I2S_AD0_A0_17: C20.2 MSP1.6 R33.2 | length 689.6
  Top Layer w8: R33.2@921.69,2542.28 920.7,2542.28 874.38,2495.95 874.38,2495.57 859.68,2480.87 C20.2@858.69,2480.87 857.71,2480.87 799.01,2422.16 799.01,2369.6 1001.65,2166.96 1001.65,2073.04 982.82,2054.21 MSP1.6@925.59,2054.21
7_PA14_I2S_AD1_A0_16: C22.2 MSP1.7 R35.2 | length 954.8
  Top Layer w8: v1(833.59,2383.8) 836.63,2386.84 1002.19,2386.84 1058,2442.66 C22.2@1058,2480.87 1057.01,2480.87 1042.31,2495.57 1042.31,2495.95 995.99,2542.28 R35.2@995,2542.28 ; MSP1.7@925.59,2034.53 1001.65,2034.53 1026.2,2059.08 1026.2,2099.61 1056.07,2129.48 v1(1059.34,2129.48)
  Bottom Layer w8: v1(833.59,2383.8) 833.59,2335.95 905.97,2263.56 964.8,2263.56 1059.34,2169.01 v1(1059.34,2129.48)
8_PA15_I2S_WCLK_A0_15: C16.2 MSP1.8 R29.2 | length 761.7
  Top Layer w8: MSP1.8@925.59,2014.84 1030.24,2014.84 1132.01,2116.61 1132.01,2132.96 1164.87,2165.81 v1(1166.95,2165.81) ; v1@1110.68,2315.14 1110.68,2316.15 1097.23,2329.6 1097.23,2447.7 1130.33,2480.8 1131.85,2480.8 1193.32,2542.28 R29.2@1194.31,2542.28
  Bottom Layer w8: v1(1110.68,2314.91) 1168.64,2256.95 1168.64,2167.51 v1(1166.95,2165.81)
9_PA16_I2S_MCLK_A0_14: C24.2 MSP1.9 R36.2 | length 908
  Top Layer w8: MSP1.9@925.59,1995.16 1050.02,1995.16 v1(1168.21,2113.35) ; v1(1124.25,2428.48) 1145.65,2449.88 1235.66,2449.88 1266.64,2480.87 1268.61,2480.87 1314.93,2527.19 1314.93,2527.64 1329.63,2542.34 R36.2@1330.62,2542.34
  Bottom Layer w8: v1(1124.25,2428.48) 1124.25,2349.25 1203.59,2269.91 1203.59,2148.73 v1(1168.21,2113.35)
10_PA17_RGBLED: J12.2 MSP1.10 | length 2288.7
  Top Layer w8: MSP1.10@925.72,1975.6 977.97,1975.6 989.51,1964.06 v1(992.66,1964.06)
  VCC Layer w8: v1(282.3,765.05) 320.72,803.47 320.72,1248.99 523.29,1451.56 523.29,1985.79 v1(523.99,1986.49)
  Bottom Layer w8: v1(282.3,765.05) 282.3,555.03 302.31,535.02 302.31,434.32 J12.2@357.01,379.62 ; v1(523.99,1986.49) 525.31,1987.81 965.92,1987.81 989.67,1964.06 v1(992.66,1964.06)
11_PA18_BSL_Invoke: MSP1.11 R22.2 | length 736.6
  Top Layer w8: v1(583.93,1624.86) 644.88,1624.86 R22.2@646.74,1626.72 ; v1(845.53,1955.93) 845.6,1955.86 925.52,1955.86 MSP1.11@925.59,1955.79
  VCC Layer w8: v1(582.93,1953.88) 583.43,1953.38 583.43,1625.36 v1(583.93,1624.86)
  Bottom Layer w8: v1(582.93,1953.88) 583.96,1954.9 844.51,1954.9 v1(845.53,1955.93)
12_PA19_SWDIO: J101.14 J103.2 MSP1.12 U3.7 | length 1934.1
  Top Layer w8: MSP1.12@925.59,1936.1 1038.99,1936.1 1091.82,1988.94 v1(1091.82,1991) ; J101.14@1041.04,2840 1132.24,2748.8 U3.7@1491.35,2748.8 ; U3.7@1493.54,2747.88 1493.54,2724.63 1510.41,2707.76 1645.09,2707.76 1689.43,2752.11 1689.43,2792.55 J103.2@1700,2803.12
  VCC Layer w8: v1(937.2,2673.76) 939.71,2671.26 939.71,2431.57 v1(942.21,2429.07)
  Bottom Layer w8: v1(937.2,2673.76) 937.2,2736.16 J101.14@1041.04,2840 ; v1(942.21,2429.07) 1031.37,2339.91 1031.37,2303.16 1091.95,2242.58 v1@1091.95,1991.12
13_PA20_SWCLK: J101.16 J103.4 MSP1.13 U3.6 | length 2262.9
  Top Layer w8: MSP1.13@925.59,1916.42 1063.25,1916.42 1127.65,1980.82 v1(1127.65,2027.77) ; U3.6@1491.35,2768.49 1212.55,2768.49 J101.16@1141.04,2840 1181.55,2880.51 1712.96,2880.51 1750,2843.47 J103.4@1750,2803.12
  VCC Layer w8: v1(997.18,2422.31) 997.25,2422.38 997.25,2691.52 v1(997.33,2691.59)
  Bottom Layer w8: v1(997.18,2422.31) 1065.86,2353.63 1065.86,2313.14 1127.12,2251.88 1127.12,2028.3 v1(1127.65,2027.77) ; v1(997.33,2691.59) 997.33,2693.94 1141.04,2837.65 J101.16@1141.04,2840
14_PB17_UC2_PICO: J2/J4.15 J16.3 MSP1.14 | length 3221.3
  Top Layer w8: MSP1.14@925.59,1896.73 969.95,1896.73 v1@990.72,1875.96 ; v1(1375.61,347.01) 1375.61,346.48 1389.76,332.33 J16.3@1389.76,199.95
  VCC Layer w8: v1(990.72,1875.08) 990.24,1874.6 990.24,1851.87 911.89,1773.52 911.89,1475.49 1094.01,1293.37 1094.01,625.59 1283.13,436.48 1356.39,436.48 1375.61,417.27 v1(1375.61,347.01)
  Bottom Layer w8: v1(990.72,1875.08) 1021.36,1875.08 1111.38,1965.1 1480.4,1965.1 1541.74,1903.76 1708.58,1903.76 1752.2,1947.38 1837.01,1947.38 1929.28,1855.11 2000.11,1855.11 J2/J4.15@2050,1905
15_PB18_UC2_SCK: J1/J3.7 J16.5 MSP1.15 | length 3693.9
  Top Layer w8: J1/J3.7@250,1805 299.2,1755.8 826.12,1755.8 875.54,1805.22 875.54,1864.27 888.3,1877.03 MSP1.15@925.59,1877.05 ; v1(1253.21,309.3) 1253.21,265.75 1291.4,227.55 1291.4,217.7 J16.5@1303.15,205.95
  VCC Layer w8: v1(132.61,307.37) 87.2,352.78 87.2,1785.04 107.16,1805 J1/J3.7@250,1805
  Bottom Layer w8: v1(132.61,307.37) 132.77,307.21 1251.12,307.21 v1(1253.21,309.3)
16_PB19_UC2_POCI: J2/J4.14 J16.7 MSP1.16 | length 3478.3
  Top Layer w8: v1@626.51,1727.78 833.95,1727.78 925.59,1819.42 MSP1.16@925.59,1857.36 ; v1(1140.48,424.91) 1216.54,348.85 J16.7@1216.54,199.95
  VCC Layer w8: v1(994.47,1501.35) 1506.76,1501.35 v1(1602.38,1596.97)
  Bottom Layer w8: v1@623.29,1728.16 829.88,1728.16 994.47,1563.57 v1(994.47,1501.35) 994.47,1436.7 1173.83,1257.34 1173.83,458.27 v1(1140.48,424.91) ; v1@1602.94,1596.97 1760.44,1754.47 1999.47,1754.47 J2/J4.14@2050,1805
  other v1: 623,1727.86
17_PA21_VREF-: C6.2 MSP1.17 R3.2 R20.2 | length 407.7
  Top Layer w8: R20.2@712.75,1626.72 720.06,1634.03 872.36,1634.03 R3.2@884.91,1646.58 ; R3.2@891.93,1647.94 893.39,1646.48 946.22,1646.48 950.37,1650.63 950.37,1754.26 976.71,1780.59 MSP1.17@1002.36,1780.59
18_PA22_CLKOUT: J2/J4.11 MSP1.18 | length 1354.8
  Top Layer w8: MSP1.18@1022.05,1780.59 1022.05,1731.71 1060.75,1693.01 1060.75,1478.61 v1(1059.3,1477.15)
  VCC Layer w8: v1(1059.3,1477.15) 1847.81,1477.15 1879.97,1445 2000,1445 2050,1495 J2/J4.11@2050,1505
19_PB20_A0_6: J21.7 MSP1.19 R27.1 | length 2488.6
  Top Layer w8: J21.7@680.54,168.18 787.73,275.38 865.07,275.38 931.41,341.72 931.41,529.5 1088.26,686.35 1525.41,686.35 1576.62,737.57 R27.1@1577.61,737.57 ; MSP1.19@1041.73,1780.59 1041.73,1741.63 1091.15,1692.21 1091.15,1438.75 v1(1129.25,1400.65)
  VCC Layer w8: v1(1129.25,1400.65) 1235.18,1400.65 1256.92,1378.91 1256.92,686.93 v1(1256.34,686.35)
20_PB21_A0_25_COMP0_IN0+: J1/J3.5 J23.2 MSP1.20 | length 3469.3
  Top Layer w8: v1(1035.4,1847.46) 1061.42,1821.45 MSP1.20@1061.42,1780.59
  VCC Layer w8: v1(1035.4,1847.46) 1033.99,1846.05 1013.91,1846.05 932.53,1764.67 932.53,1485.25 1116.26,1301.52 1116.26,635.61 1292.09,459.79 v1(1493.72,459.79)
  Bottom Layer w8: J1/J3.5@250,2005 303,2058 376.7,2058 398.71,2035.99 398.71,1903.66 423.83,1878.54 939.87,1878.54 971.82,1846.59 1034.53,1846.59 v1(1035.4,1847.46) ; v1(1493.72,459.79) 1567.96,459.79 J23.2@1958.32,69.43
21_PB22_A0_24_COMP0_IN0-: J1/J3.6 MSP1.21 | length 1010.2
  Top Layer w8: MSP1.21@1081.1,1780.59 v1@1081.1,1879.11
  Bottom Layer w8: J1/J3.6@250,1905 297.2,1857.8 927.26,1857.8 968.19,1816.88 1049.56,1816.88 1081.35,1848.68 v1@1081.35,1879.36
  other v1: 1080.24,1876.58
22_PB23: J2/J4.17 MSP1.22 | length 1302.7
  Top Layer w8: MSP1.22@1100.79,1780.59 1100.79,1848.4 1122.64,1870.26 1122.64,1928.29 1180.16,1985.81 1180.16,2081.37 1261.56,2162.77 v1(1262.66,2162.77)
  Bottom Layer w8: v1(1262.66,2162.77) 1370.59,2054.84 1993.04,2054.84 2043.2,2105 J2/J4.17@2050,2105
23_PB24_UC2_CS1: J2/J4.18 MSP1.23 | length 2133.4
  Top Layer w8: MSP1.23@1120.47,1780.59 1120.47,1458.4 1144.53,1434.34 v1(1358.03,1434.34)
  Bottom Layer w8: v1(1358.03,1434.34) 2099.07,1434.34 2137.25,1472.51 2137.25,2117.75 J2/J4.18@2050,2205
24_PA23_VREF+: C6.1 C7.1 MSP1.24 R21.2 | length 493.4
  Top Layer w8: R21.2@930.12,1506.26 937.93,1514.07 942.77,1514.07 995.38,1566.68 995.38,1567.67 1010.08,1582.37 C7.1@1011.06,1582.37 1005.2,1588.23 v1(1005.2,1703.33) ; MSP1.24@1140.34,1780.77 1140.51,1780.94 1140.51,1841.97 v1(1140.87,1842.32)
  Bottom Layer w8: v1(1005.2,1703.33) 1140.87,1838.99 v1(1140.87,1842.32)
25_PA24_RGBLED: J13.2 MSP1.25 | length 2262.4
  Top Layer w8: v1(1148.77,1679) 1147.98,1679.79 1147.98,1725.64 1160.03,1737.69 MSP1.25@1160.03,1780.4
  VCC Layer w8: v1(346.48,775.33) 346.48,1237.52 553.85,1444.89 v1@553.85,1704.66
  Bottom Layer w8: v1(346.48,775.33) 410.93,710.88 410.93,433.54 J13.2@464.85,379.62 ; v1(554.26,1705.06) 556.64,1705.06 605.04,1753.46 832.22,1753.46 967.4,1618.29 1088.05,1618.29 v1(1148.77,1679)
26_PA25_A0_2: C23.2 MSP1.26 R34.2 | length 919
  Top Layer w8: v1(623,1825.22) 625.19,1825.22 661.63,1861.66 R34.2@721.06,1861.66 ; R34.2@721.22,1861.82 C23.2@783.43,1861.82 ; v1(1163.67,1910.16) 1179.53,1894.3 MSP1.26@1179.53,1780.59
  Bottom Layer w8: v1(623,1825.22) 625.28,1825.22 655.7,1794.81 1057.24,1794.81 1108.54,1846.1 1108.54,1857.18 1161.52,1910.16 v1(1163.67,1910.16)
27_PB25_TIMA_FAL0_COMP0_OUT: J1/J3.8 MSP1.27 | length 1160.2
  Top Layer w8: v1(1182.42,1713.82) 1182.42,1717.01 1199.21,1733.8 MSP1.27@1199.21,1780.59
  Bottom Layer w8: J1/J3.8@250,1705 299.61,1655.39 371.85,1655.39 490.5,1774.04 845.98,1774.04 977.89,1642.12 1067.97,1642.12 1139.66,1713.82 v1(1182.42,1713.82)
28_PB26: J2/J4.19 MSP1.28 | length 1223.8
  Top Layer w8: MSP1.28@1218.9,1780.59 1217.94,1781.55 1217.94,2071.85 v1(1403.26,2257.17)
  Bottom Layer w8: v1(1403.26,2257.17) 1405.78,2254.64 2002.14,2254.64 2050,2302.49 J2/J4.19@2050,2305
29_VUSB: C8.2 C9.2 J101.20 MSP1.29 | length 1748.9
  Top Layer w8: MSP1.29@1238.58,1780.59 1238.58,1714.71 1238.64,1714.65
  Top Layer w12: v1@1195.13,1556.19 v1(1193.09,1554.14) 1250.33,1554.14 ; 1252.38,1556.19 1261.44,1565.25 1261.44,1607.8 C8.2@1262.43,1608.79
  VCC Layer w12: v1(1193.09,1554.14) 1215.49,1576.54 1215.49,2278.61 v1(1534.88,2598)
  Bottom Layer w12: J101.20@1341.04,2840 1440.6,2840 1534.88,2745.72 v1(1534.88,2598)
30_PA26_DM: J105.A7 J105.B7 MSP1.30 R92.1 U4.1 U4.10 | length 2020.4
  Top Layer w9.6: v5@1865.42,691.72 1876.03,702.33 1898.21,702.33 1899.02,701.52 U4.10@1913.61,701.52 ; U4.10@1914.47,701.52 U4.1@1947.34,701.52 ; U4.1@1948.21,701.52 1956.54,701.52 1957.72,702.7 1977.28,702.7 1994.56,702.7 2031.1,702.7 J105.B7@2031.17,702.62 2031.25,702.7 2061.32,702.7 2066.95,697.07 2066.95,660.93 2061.32,655.3 2031.25,655.3 J105.A7@2031.17,655.38
  Top Layer w11.6: MSP1.30@1258.35,1804.12 v5@1258.35,1836.59
  Bottom Layer w11.6: v5@1258.29,1836.59 1258.29,810.15 1368.11,700.33 1656.7,700.33 1687.52,669.51 R92.1@1688.5,669.51 1689.49,669.51 1720.31,700.33 1848.15,700.33 1850.98,697.5 1862.56,697.5 v5(1864.93,695.13)
  other v5: 1252.95,1840
31_PA27_DP: J105.A6 J105.B6 MSP1.31 R91.1 U4.2 U4.9 | length 2039.9
  Top Layer w9.6: v5@1865.42,728.54 1876.03,717.93 1897.47,717.93 1899.02,719.48 U4.9@1913.61,719.48 ; U4.9@1914.47,719.48 U4.2@1947.34,719.48 ; U4.2@1948.21,719.48 1956.54,719.48 1957.73,718.3 2031.1,718.3 J105.B6@2031.17,718.37 2031.25,718.3 2067.78,718.3 2082.55,703.53 2082.55,654.47 2067.78,639.7 2031.25,639.7 J105.A6@2031.17,639.63
  Top Layer w11.6: MSP1.31@1277.95,1804.12 v5@1277.95,1836.59
  Bottom Layer w11.6: v5@1277.88,1836.59 1277.88,818.27 1376.22,719.93 1656.7,719.93 1687.52,750.75 R91.1@1688.5,750.75 1689.49,750.75 1720.31,719.93 1848.15,719.93 1850.98,722.76 1862.56,722.76 v5(1864.93,725.13)
  other v5: 1283.31,1840
32_VCORE: C3.1 C4.1 MSP1.32 | length 146.4
  Top Layer w10: MSP1.32@1297.64,1780.59 1297.64,1739.27 1334.8,1702.11 C3.1@1338.74,1702.11 1338.74,1655.39 C4.1@1340.04,1654.1
33_PA0_UC1_SDA_TX: J2/J4.32 J9.2 MSP1.33 R13.1 | length 2918.9
  Top Layer w8: R13.1@1349.18,1333.43 1349.18,1337.37 1356.99,1345.18 1411.89,1400.08 v1(1440.65,1400.08) 1439.99,1400.74 1439.99,1559.3 v1(1439.34,1559.96) 1439.34,1727.21 1374.8,1791.75 MSP1.33@1374.8,1857.36
  VCC Layer w8: v1(1333.16,573.81) 1333.16,918.4 1440.65,1025.89 v1(1440.65,1400.08)
  Bottom Layer w8: J9.2@572.69,379.62 623.3,329.01 1139.62,329.01 1333.16,522.55 v1(1333.16,573.81) ; v1(1439.34,1559.96) 1757.91,1559.96 1802.96,1605 J2/J4.32@1950,1605
34_PA1_UC1_SCL_RX: J2/J4.31 MSP1.34 R18.1 | length 1168.7
  Top Layer w8: MSP1.34@1374.41,1877.05 1408.3,1877.04 1417.24,1868.1 1417.24,1779.44 1486.12,1710.56 1800.56,1710.56 1880.11,1631 1880.11,1574.89 J2/J4.31@1950,1505 1950,1273.43 1911.98,1235.41 1843.36,1235.41 R18.1@1843.19,1235.24
35_PA28_TIMA0_C3: J2/J4.36 MSP1.35 | length 912.2
  Top Layer w8: v1(1308.11,1929.32) 1339.92,1897.51 1373.64,1897.51 MSP1.35@1374.41,1896.73 ; v1(1800.54,1892.66) 1800.54,1943.5 1862.05,2005 J2/J4.36@1950,2005
  Bottom Layer w8: v1(1308.11,1929.32) 1464.34,1773.09 1680.97,1773.09 v1(1800.54,1892.66)
36_PA29_UC2_CS3: J2/J4.12 MSP1.36 | length 861.8
  Top Layer w8: MSP1.36@1374.41,1916.42 1375.62,1915.2 1408.46,1915.2 1436.11,1887.54 1436.11,1789.94 1494.24,1731.81 1823.83,1731.81 1900.34,1655.3 1999.7,1655.3 J2/J4.12@2050,1605
37_PA30_UC2_CS2: J2/J4.13 MSP1.37 | length 824.4
  Top Layer w8: MSP1.37@1374.41,1936.1 1411.33,1936.1 1454.34,1893.09 1454.34,1802.44 1502.57,1754.22 2000.78,1754.22 J2/J4.13@2050,1705
39_PA31_TIMA0_C3N: J2/J4.35 MSP1.39 | length 814.1
  Top Layer w8: v1(1277.57,1994.24) 1296.55,1975.25 1374.08,1975.25 MSP1.39@1374.31,1975.47
  Bottom Layer w8: v1(1277.57,1994.24) 1485.43,1994.24 1510.43,1969.23 1885.77,1969.23 J2/J4.35@1950,1905
42_PA2_ROSC: MSP1.42 R8.1 R9.2 | length 993.2
  Top Layer w8: v1(1305.1,2068.31) 1338.88,2034.53 MSP1.42@1373.42,2034.53 ; R8.1@1665.8,1853.76 1665.91,1853.65 1704.32,1853.65 v1(1704.44,1853.53) 1743.58,1892.68 v1(1743.58,2004) ; R9.2@1667.95,1655.3 1672.38,1650.86 v1(1703.27,1650.86)
  VCC Layer w8: v1(1703.27,1650.86) 1703.85,1651.45 1703.85,1852.95 v1(1704.44,1853.53)
  Bottom Layer w8: v1(1305.1,2068.31) 1349.24,2024.17 1723.42,2024.17 v1(1743.58,2004)
43_PA3_LFXIN: C10.1 MSP1.43 R10.2 Y1.2 | length 445.4
  Top Layer w8: MSP1.43@1374.41,2054.21 1475.34,2054.21 1498.57,2030.99 1498.57,2030.87 1514.25,2015.19 1545.75,2015.19 1573.42,1987.52 C10.1@1605,1987.55 1604.86,1987.4 1604.86,1937.7 v1(1604.71,1937.56) ; R10.2@1694.83,1982.55 1695,1982.37 1695,1936.72 v1(1695.18,1936.55)
  Bottom Layer w8: v1(1604.71,1937.56) 1605.22,1937.05 1694.67,1937.05 v1(1695.18,1936.55)
44_PA4_LFXOUT: C13.1 MSP1.44 R11.2 Y1.1 | length 414.2
  Top Layer w8: MSP1.44@1374.41,2073.9 1475.53,2073.9 1498.57,2096.94 1498.57,2097.93 1514.25,2113.61 Y1.1@1530,2113.61 ; Y1.1@1544.68,2113.61 1575,2143.93 C13.1@1605,2143.93 ; C13.1@1609.43,2143.56 v1(1649.75,2143.56) ; R11.2@1694.83,2147.96 1699.23,2143.56 v1(1735.57,2143.56)
  Bottom Layer w8: v1(1649.75,2143.56) v1(1735.57,2143.56)
45_PA5_HFXIN: C12.1 MSP1.45 R14.2 Y2.3 | length 358.9
  Top Layer w8: MSP1.45@1374.68,2093.31 1430.21,2093.31 1495.57,2158.67 1530.35,2158.67 1577.5,2205.83 Y2.3@1577.5,2210.75 1624.43,2210.75 C12.1@1629.05,2215.36 ; C12.1@1631.61,2212.79 1631.83,2212.57 R14.2@1682.61,2212.57
46_PA6_HFXOUT: C11.1 MSP1.46 R17.2 Y2.1 | length 377.1
  Top Layer w8: MSP1.46@1374.41,2113.27 1415.44,2113.27 1464.94,2162.77 1464.94,2242.88 1514.5,2292.44 Y2.1@1514.5,2297.36 1514.5,2407.26 R17.2@1513.74,2408.02
47_PB0_TIMA0_C2: J2/J4.38 MSP1.47 | length 656.7
  Top Layer w8: MSP1.47@1374.58,2133.12 1376.31,2134.86 1405.06,2134.86 1431.51,2161.31 1431.51,2195.94 1431.41,2196.05 1431.41,2220.88 v1(1430.25,2222.05)
  Bottom Layer w8: v1(1430.25,2222.05) 1447.29,2205 J2/J4.38@1950,2205
48_PB1_TIMA0_C2N: J2/J4.37 MSP1.48 | length 650
  Top Layer w8: MSP1.48@1374.41,2152.64 1374.41,2180.07 1392.48,2198.15 v1(1392.48,2198.77)
  Bottom Layer w8: v1(1392.48,2198.77) 1408.75,2182.5 1872.5,2182.5 J2/J4.37@1950,2105
49_PA7_BUTTON: J10.2 MSP1.49 | length 966.5
  Top Layer w8: MSP1.49@1297.64,2229.41 1297.64,2238.83 1299.54,2240.73 1322.46,2240.73 v1(1348.95,2267.22)
  Bottom Layer w8: v1(1348.95,2267.22) 1377.03,2295.3 1518.68,2295.3 1864.66,2641.28 J10.2@2087.98,2641.28
50_PB2_UC3_PICO_TX: J1/J3.4 MSP1.50 | length 1905.1
  Top Layer w8: MSP1.50@1277.95,2229.41 1279.8,2231.26 1279.8,2262.82 1330,2313.02 1355.1,2313.02 1412.89,2370.8 v1(1412.89,2421.86)
  Bottom Layer w8: 229.78,2128.27 177.33,2180.71 177.33,2449.33 240.51,2512.51 1322.24,2512.51 v1(1412.89,2421.86)
51_PB3_UC3_SCK_RX: J1/J3.3 MSP1.51 | length 1510.6
  Top Layer w8: MSP1.51@1258.27,2229.41 1258.27,2268.53 v1(1382.48,2392.74)
  Bottom Layer w8: J1/J3.3@250,2205 300.23,2255.23 397.67,2255.23 636.05,2493.61 1285.07,2493.61 1382.48,2396.2 v1(1382.48,2392.74)
52_PB4_TIMA0_C1: J2/J4.40 MSP1.52 | length 861.3
  Top Layer w8: MSP1.52@1238.58,2229.41 1238.58,2286.67 1409.55,2457.64 1897.36,2457.64 J2/J4.40@1950,2405
53_PB5_TIMA0_C1N: J2/J4.39 MSP1.53 | length 1084.4
  Top Layer w8: MSP1.53@1218.9,2229.41 1218.9,2295.27 1400.31,2476.69 1947.71,2476.69 2000.64,2423.76 2000.64,2355.64 J2/J4.39@1950,2305
54_PA8_UC1_SDA_TX: J1/J3.10 MSP1.54 R25.2 | length 3071.9
  Top Layer w8: MSP1.54@1199.21,2229.41 1199.21,2313.97 v1@1299.87,2414.62 ; v1(1438.55,2654.38) 1438.55,2653.67 1488.69,2603.54 R25.2@1488.69,2596.2
  VCC Layer w8: v1(1299.87,2415.12) 1439.12,2554.37 1439.12,2653.82 v1(1438.55,2654.38)
  Bottom Layer w8: J1/J3.10@250,1505 87.7,1667.3 87.7,2486.01 196.51,2594.82 1054.82,2594.82 1114.39,2654.38 v1(1438.55,2654.38)
55_PA9_UC1_SCL_RX: J1/J3.9 MSP1.55 R24.2 | length 2793.4
  Top Layer w8: MSP1.55@1179.53,2229.41 1179.54,2336.22 1190.67,2347.35 v1(1190.67,2350.91) ; v1(1400.48,2598.3) 1439.38,2598.3 R24.2@1440.68,2599.6
  VCC Layer w8: v1(1190.67,2350.91) 1400.48,2560.72 v1(1400.48,2598.3)
  Bottom Layer w8: J1/J3.9@250,1605 111.16,1743.84 111.16,2476.61 207.56,2573.01 1066.37,2573.01 1120.19,2626.83 1371.73,2626.83 v1@1400.26,2598.3
56_PA10_UC0_SDA_TX: J2/J4.34 J101.10 MSP1.56 | length 2821
  Top Layer w8: MSP1.56@1159.84,2229.41 1159.84,2364.66 1210.23,2415.04 v1(1211.18,2415.04)
  VCC Layer w8: v1(1626.9,2548.46) 1627.47,2547.9 1857.22,2547.9 1897.41,2507.71 1897.41,1850.01 1942.42,1805 J2/J4.34@1950,1805
  Bottom Layer w8: J101.10@841.04,2840 883.91,2882.87 1436.68,2882.87 1626.9,2692.66 v1(1626.9,2548.46) 1626.9,2485.14 1481.25,2339.5 1286.73,2339.5 v1(1211.18,2415.04)
57_PA11_UC0_SCL_RX: J2/J4.33 J101.8 MSP1.57 | length 3119.7
  Top Layer w8: MSP1.57@1140.29,2229.54 1140.29,2393.53 1164.94,2418.18 v1(1165.68,2418.18)
  VCC Layer w8: v1(1660.55,2511.89) 1851.11,2511.89 1874.37,2488.63 1874.37,1723.43 1892.8,1705 J2/J4.33@1950,1705
  Bottom Layer w8: J101.8@741.04,2840 798.95,2897.91 1457.62,2897.91 1660.55,2694.98 v1(1660.55,2511.89) 1660.73,2511.71 1660.73,2477.6 1500.45,2317.32 1266.54,2317.32 v1(1165.68,2418.18)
